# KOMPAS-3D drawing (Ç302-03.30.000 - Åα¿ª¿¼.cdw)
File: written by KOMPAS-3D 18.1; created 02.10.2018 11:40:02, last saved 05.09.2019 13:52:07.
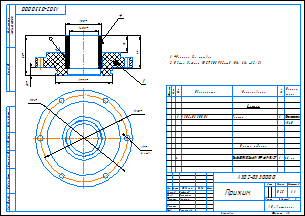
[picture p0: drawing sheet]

Sheet 1: A3, landscape

Document properties: Автор: Милов; Полное имя файла: \\192.168.87.28\Konstructor_doc\Мембранные насосы\Мембранный электропривод\А302-00.00.000 - ASTRA-302 (МЭ200)\3Д ПВХ\А302-01.30.000 - Прижим.a3d; Масса: 0.250005

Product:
- Part/product: (unnamed)
  - Component: Прижим  | designation А302-03.30.001  | pos. 1  | Раздел спецификации: Детали; Примечание: Полипропилен / @2~140
  - Component: Труба 50 PN10 S=4,6 FV PPR ф. FV PLAST  | pos. 4  | Раздел спецификации: Прочие изделия; Примечание: 46 мм

Title block, sheet 1: Наименование: Прижим; designation: А302-03.30.000; Масса: 0,25; scale: 1:1; Количество листов документа: 1; organisation: АО «Астерион»; Форматы листов документа: A3; stored path: \\192.168.87.28\Konstructor_doc\Мембранные насосы\Мембранный электропривод\А302-00.00.000 - ASTRA-302 (МЭ200)\3Д ПВХ\А302-01.30.000 - Прижим.cdw; Разработал: Лифлянд; Проверил: Борисенко; Т. контр.: Лучихин; Утвердил: Григорьева

Views: Вид 1, Местный разрез 1, Вид:1
Referenced files in D:\Мембранные насосы\Мембранный электропривод\А302-00.00.000 - ASTRA-302 (МЭ200)\3Д ПВХ\: А302-01.30.001 - Прижим.m3d, А302-01.30.000 - Прижим.a3d, А302-01.30.001 - Прижим.cdw
Referenced files in D:\1 ПКИ 3D\Полипропиленовые фитинги, трубы\Трубы\: Труба 50 PN10 S=4,6 FV PPR ф. FV PLAST.m3d
Referenced files in \\192.168.87.28\Konstructor_doc\Мембранные насосы\Мембранный электропривод\А302-00.00.000 - ASTRA-302 (МЭ200)\3Д ПВХ\: А302-01.30.001 - Прижим.m3d, А302-01.30.001 - Прижим.cdw
Referenced files in \\192.168.87.28\Konstructor_doc\Мембранные насосы\Мембранный электропривод\А302-00.00.000 - ASTRA-302 (МЭ200)\3Д ПВХ\Отработка\: Труба ПВХ PN10 50х2,4.m3d
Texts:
  Труба ПВХ PN10 50х2,4
  Труба 50 PN10 S=4,6 FV PPR ф. FV PLAST
  Полипропилен
  Полипропилен / @2~140
Dimensions and other numbers on the sheet: 46; 55; 77,9; 10; 1; 4; 23; 40,8; 50; 61; -02; 46 мм; 1:1; 0,25; 01

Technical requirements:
  *Размеры для справок.
  Общие допуски ГОСТ 30893.2-mK (H14, h14,  t2/2).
